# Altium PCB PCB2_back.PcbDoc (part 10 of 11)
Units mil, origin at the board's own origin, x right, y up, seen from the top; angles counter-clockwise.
Board outline 6299 x 3937 mil, 4 copper layers (TopLayer, GROUND, VCC, BottomLayer); 290 components, 470 nets, 2252 pads, 825 vias.
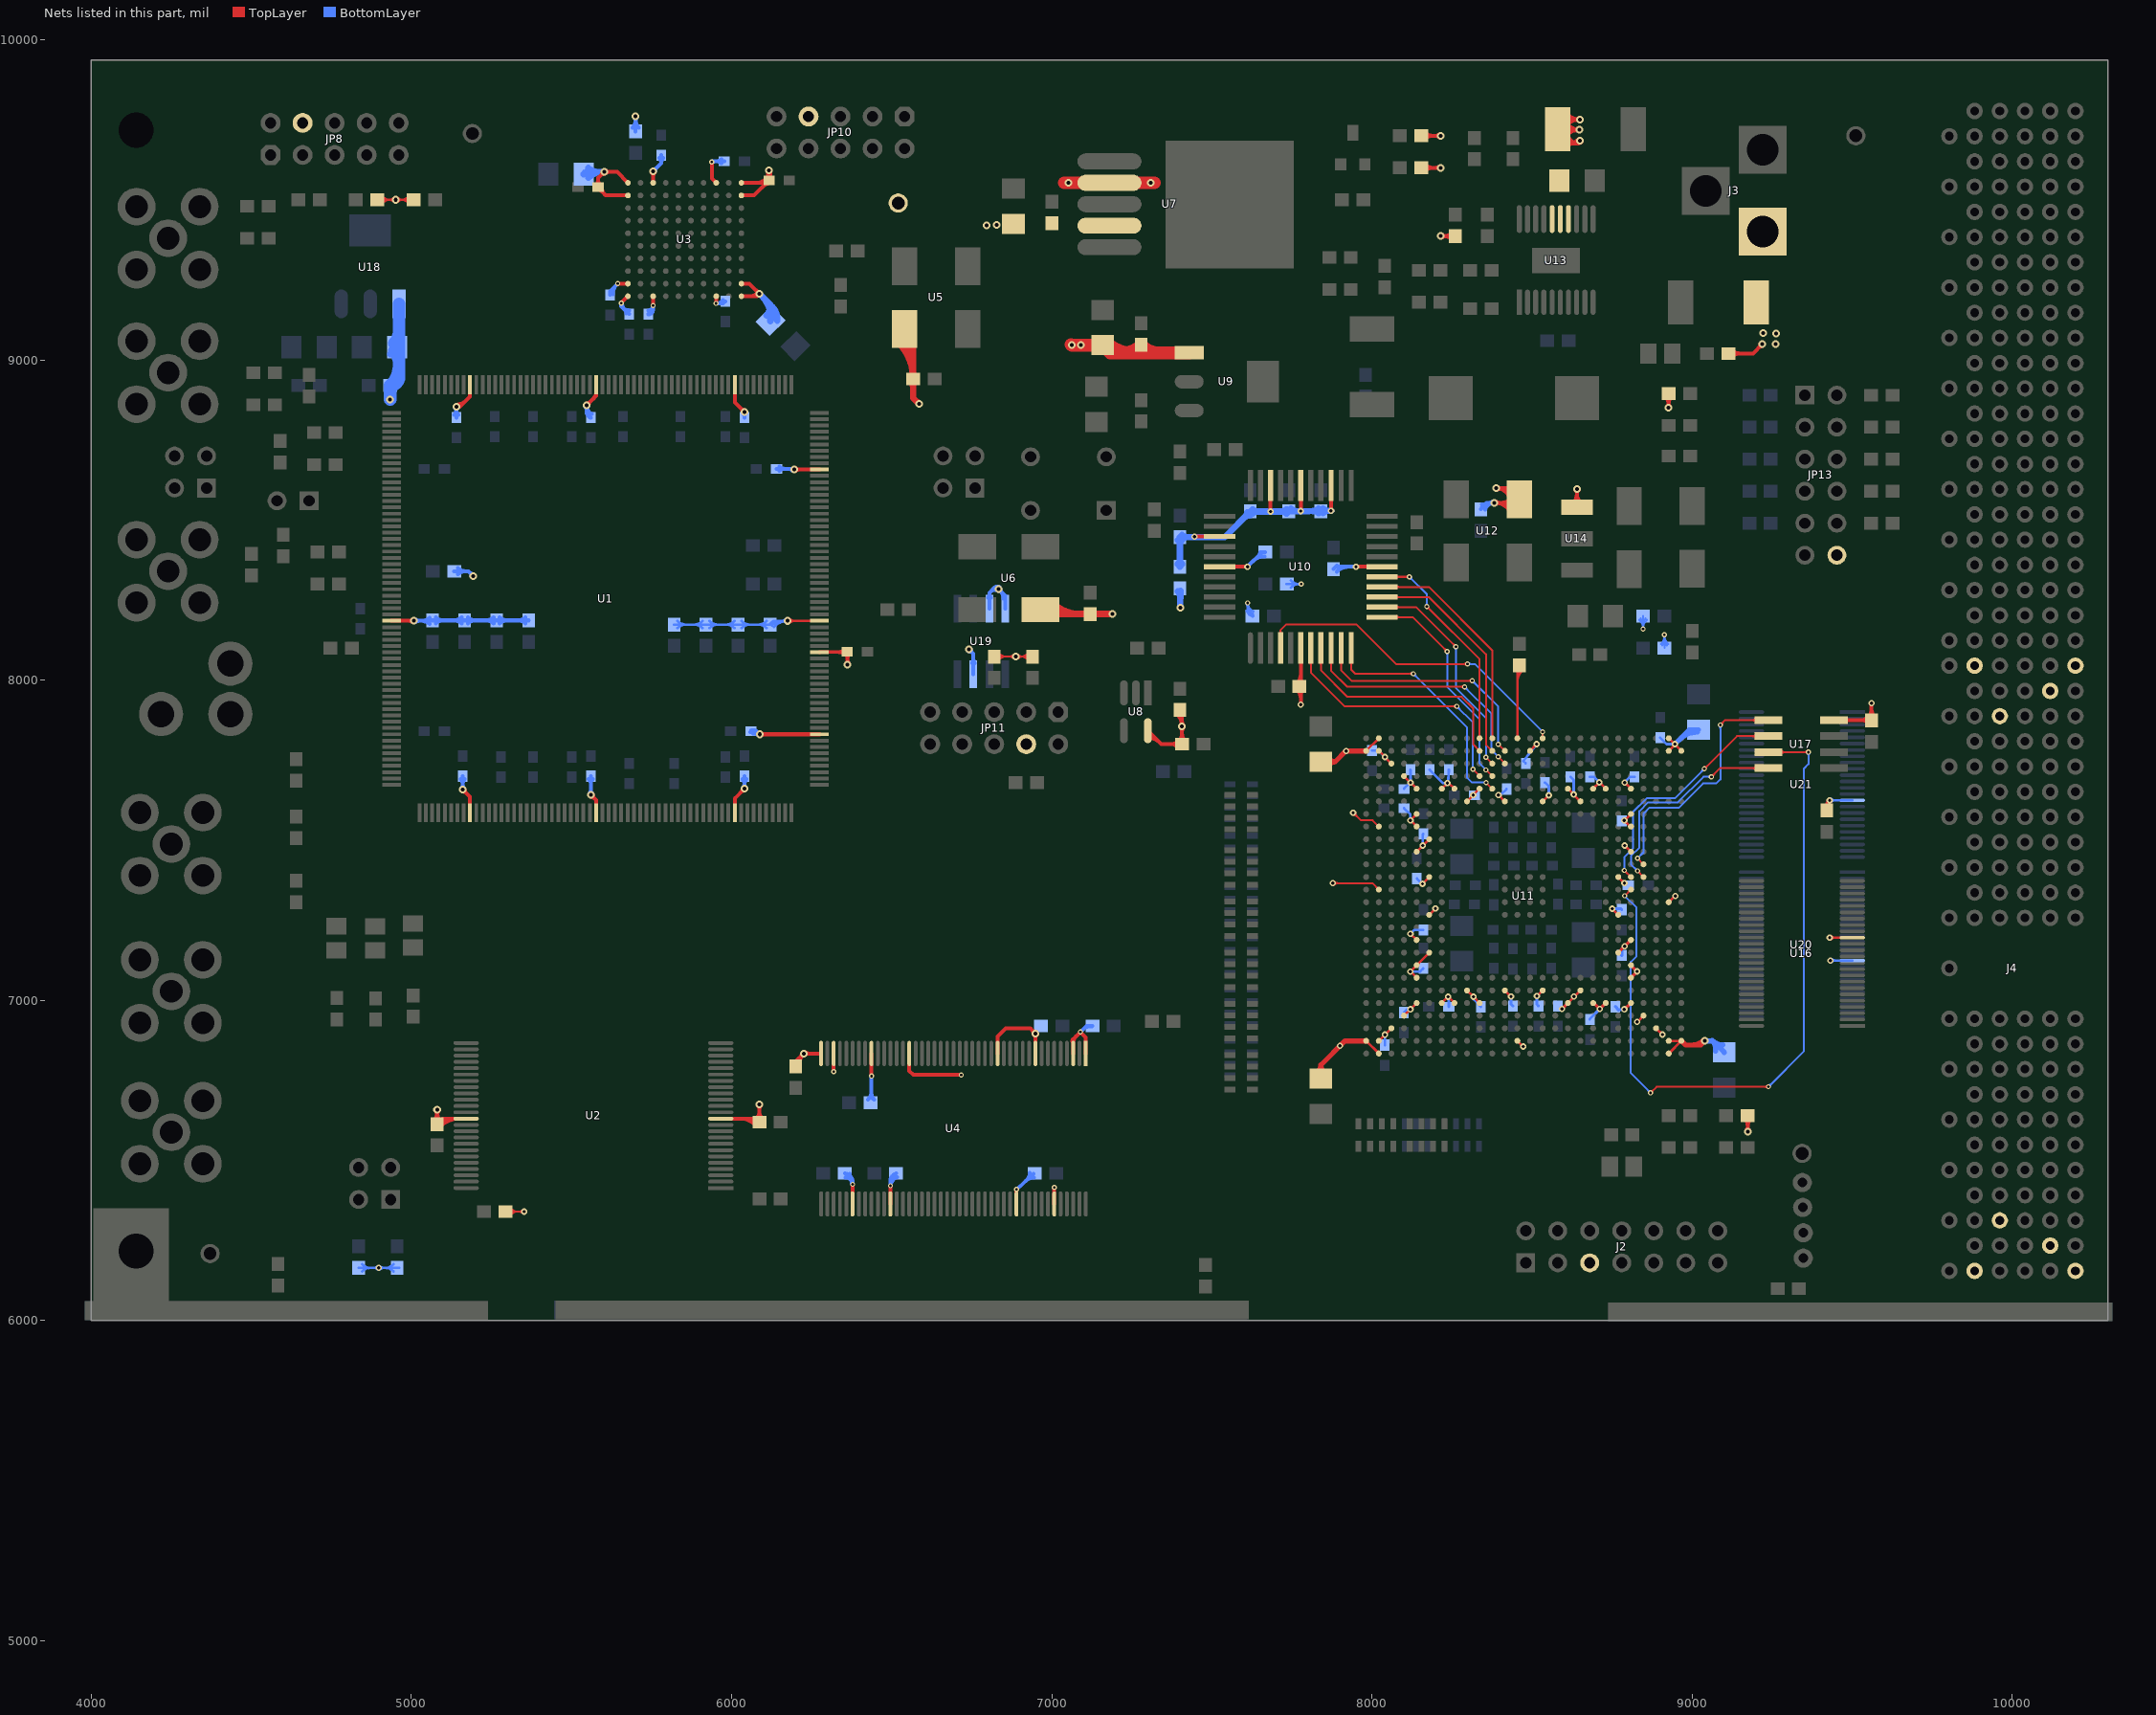
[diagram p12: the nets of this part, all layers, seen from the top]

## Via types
v1: diameter 16, hole 8, TopLayer to BottomLayer, 408 vias
v2: diameter 20, hole 10, TopLayer to BottomLayer, 221 vias
v3: diameter 24, hole 12, TopLayer to BottomLayer, 194 vias
v4: diameter 56.69, hole 56.69, TopLayer to BottomLayer, 2 vias

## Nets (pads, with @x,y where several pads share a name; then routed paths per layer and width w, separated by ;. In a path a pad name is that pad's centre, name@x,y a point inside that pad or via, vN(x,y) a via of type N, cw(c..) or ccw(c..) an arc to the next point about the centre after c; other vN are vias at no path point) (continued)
V3.3: C5.2 C6.2 C7.1 C8.2 C9.2 C10.1 C11.2 C12.1 C15.2 C16.2 C19.2 C20.1 C21.1 C22.2 C37.2 C44.1 C48.1 C55.1 C56.1 C57.1 C59.2 C62.2 C65.2 C66.2 C70.2 C71.1 C73.1 C74.2 C75.1 C77.1 C78.1 C79.2 C80.2 C81.2 C82.2 C83.2 C84.2 C86.2 C89.2 C91.1 C93.1 C94.1 C95.1 C96.1 C97.1 C98.1 C99.1 C100.1 C101.1 C102.1 C103.1 C108.1 C109.1 C110.1 C116.1 C117.2 C119.1 C120.1 C127.1 C128.1 C132.1 C133.1 C134.1 C139.1 C140.1 C141.1 C142.1 C143.1 C144.1 C145.1 C146.1 C147.1 FB4.1 FB8.2 J2.5 JP8.4 JP10.7 JP11.4 pad.9 R15.2 R18.2 R19.2 R24.2 R26.2 R30.2 R56.2 R63.1 R64.1 R65.2 R66.2 R76.1 R77.1 R80.2 R81.2 R82.2 U1.9 U1.22 U1.51 U1.70 U1.92 U1.112 U1.189 U1.209 U1.231 U2.12 U2.37 U3.A1 U3.A3 U3.A8 U3.A10 U3.B1 U3.B10 U3.J1 U3.J10 U3.K1 U3.K3 U3.K8 U3.K10 U4.1 U4.3 U4.9 U4.15 U4.29 U4.35 U4.41 U4.43 U4.49 U4.55 U4.75 U4.81 U5.4 U6.4 U7.4 U8.5 U10.6 U10.17 U10.39 U11.A2 U11.A25 U11.AA9 U11.AA12 U11.AA15 U11.AA18 U11.AB5 U11.AB7 U11.AB8 U11.AB10 U11.AB17 U11.AB19 U11.AB20 U11.AB22 U11.AC23 U11.AD24 U11.AE1 U11.AE2 U11.AE13 U11.AE25 U11.AE26 U11.AF2 U11.AF25 U11.B1 U11.B2 U11.B14 U11.B25 U11.B26 U11.C3 U11.C24 U11.D4 U11.D23 U11.E5 U11.E7 U11.E8 U11.E10 U11.E17 U11.E19 U11.E20 U11.E22 U11.F9 U11.F12 U11.F15 U11.F18 U11.G5 U11.G22 U11.H5 U11.H22 U11.J6 U11.J21 U11.K5 U11.K22 U11.M6 U11.M21 U11.N2 U11.P25 U11.R6 U11.R21 U11.U5 U11.U22 U11.V21 U11.W5 U11.W22 U11.W25 U11.Y5 U11.Y22 U12.4 U14.1 U17.8 U19.3 U19.7 U19.8 | length 16963.2
  TopLayer w6: 5124.53,6630.53 U2.37@5170.72,6630.53 ; U2.37@5135.21,6628.48 ccw(c5130.25,6623.52) 5130.25,6630.53 ccw(c5130.25,6637.55) U2.37@5135.21,6632.59 ; R19.2@5293.46,6340 v2(5352,6340) ; R19.2@5302.99,6332.44 cw(c5321.23,6314.2) 5321.23,6340 cw(c5321.23,6365.8) R19.2@5302.99,6347.56 ; R19.2@5307.23,6328.2 cw(c5335.71,6299.72) 5335.71,6340 cw(c5335.71,6380.28) R19.2@5307.23,6351.8 ; v2@5347.05,6335.05 ccw(c5335.1,6323.1) 5335.1,6340 ccw(c5335.1,6356.9) v2@5347.05,6344.95 ; R24.2@6820,8073.46 R26.2@6940,8073.46 ; R24.2@6827.56,8065.91 cw(c6845.8,8047.67) 6845.8,8073.46 cw(c6845.8,8099.26) R24.2@6827.56,8081.02 ; R24.2@6831.8,8061.67 cw(c6860.28,8033.18) 6860.28,8073.46 cw(c6860.28,8113.75) R24.2@6831.8,8085.26 ; v3@6881.64,8067.1 ccw(c6866.27,8051.74) 6866.27,8073.46 ccw(c6866.27,8095.19) v3@6881.64,8079.83 ; v3@6894.36,8067.1 cw(c6909.73,8051.74) 6909.73,8073.46 cw(c6909.73,8095.19) v3@6894.36,8079.83 ; R26.2@6928.2,8061.67 ccw(c6899.72,8033.18) 6899.72,8073.46 ccw(c6899.72,8113.75) R26.2@6928.2,8085.26 ; R26.2@6932.44,8065.91 ccw(c6914.2,8047.67) 6914.2,8073.46 ccw(c6914.2,8099.26) R26.2@6932.44,8081.02 ; v2(7877,7366) 8000.93,7366 U11.P25@8021.12,7345.81 ; v2@7881.95,7361.05 cw(c7893.9,7349.1) 7893.9,7366 cw(c7893.9,7382.9) v2@7881.95,7370.95 ; v2@7941,7579 cw(c7941,7562.1) 7952.95,7574.05 cw(c7964.9,7586) v2@7948,7586 ; v2(7941,7586) 7965,7562 8001.78,7562 U11.W25@8021.12,7542.66
  TopLayer w8: R15.2@4893.46,9500 R18.2@5006.54,9500 ; R15.2@4906.52,9488.91 cw(c4933.3,9462.13) 4933.3,9500 cw(c4933.3,9537.87) R15.2@4906.52,9511.09 ; v3@4945.34,9494.34 ccw(c4931.69,9480.69) 4931.69,9500 ccw(c4931.69,9519.31) v3@4945.34,9505.66 ; v3@4956.66,9494.34 cw(c4970.31,9480.69) 4970.31,9500 cw(c4970.31,9519.31) v3@4956.66,9505.66 ; R18.2@4993.48,9488.91 ccw(c4966.7,9462.13) 4966.7,9500 ccw(c4966.7,9537.87) R18.2@4993.48,9511.09 ; U11.B26@7981.75,6873.37 U11.A25@8021.12,6834 ; U11.AE26@7981.75,7778.88 U11.AF25@8021.12,7818.25 ; U11.B25@8021.12,6873.37 U11.C24@8060.49,6912.74 ; U11.AE25@8021.12,7778.88 U11.AD24@8060.49,7739.51 ; U11.D23@8099.86,6952.11 8119.87,6972.13 U11.E22@8139.23,6991.48 ; U11.AC23@8099.86,7700.14 U11.AB22@8139.23,7660.77 ; v2(8120,7207.56) U11.K22@8139.23,7188.33 ; U11.G22@8139.23,7070.22 8139.23,7070.41 v2(8119.64,7090) U11.J21@8178.6,7148.96 ; U11.U22@8139.23,7463.92 U11.V21@8178.6,7503.29 ; U11.W22@8139.23,7542.66 v2(8120,7561.89) 8120,7562.8 U11.Y22@8139.23,7582.03 ; v2(8157.42,7364) U11.R21@8178.6,7385.18 ; U11.M21@8178.6,7267.07 v2(8198,7286.47) ; U11.E20@8217.97,6991.48 8237.49,7011 v2(8237.82,7011) U11.E19@8257.34,6991.48 ; U11.AB20@8217.97,7660.77 v2(8235.2,7678) 8240.11,7678 U11.AB19@8257.34,7660.77 ; U11.F18@8296.71,7030.85 8297.15,7030.85 v2(8317,7011) U11.E17@8336.08,6991.48 ; U11.AA18@8296.71,7621.4 U11.AB17@8336.08,7660.77 ; v2(8395,7641.22) U11.AA15@8414.82,7621.4 ; U11.F15@8414.82,7030.85 v2(8434,7011.67) ; U11.B14@8454.19,6873.37 v2(8472,6855.56) ; U11.AE13@8493.56,7778.88 v2(8514,7800) ; v2(8515,7012.92) U11.F12@8532.93,7030.85 ; U11.AA12@8532.93,7621.4 v2(8552,7640.47) ; U11.E10@8611.67,6991.48 U11.F9@8651.04,7030.85 ; U11.AB10@8611.67,7660.77 U11.AA9@8651.04,7621.4 ; U11.AB8@8690.41,7660.77 8710,7680.36 v2(8710,7680.55) U11.AB7@8729.78,7660.77 ; v2(8750,7286.22) U11.M6@8769.15,7267.07 ; U11.R6@8769.15,7385.18 v2(8788.33,7366) ; v2(8789,7483.44) U11.U5@8808.52,7463.92 ; v2(8789,7680.29) U11.AB5@8808.52,7660.77 ; U11.W5@8808.52,7542.66 8806.85,7542.66 v2(8788,7561.51) U11.Y5@8808.52,7582.03 ; v2(8828,6932.22) U11.D4@8847.89,6952.11 ; U11.C3@8887.26,6912.74 v2(8907,6893) ; U11.A2@8926.63,6834 U11.B1@8966,6873.37 U11.B2@8926.63,6873.37 ; U11.N2@8926.63,7306.44 v2(8947,7326) ; U11.AE2@8926.63,7778.88 8946,7798.25 v2(8946,7800) ; U11.AF2@8926.63,7818.25 U11.AE1@8966,7778.88
  TopLayer w10: v2(8593.19,6973) U11.E10@8611.67,6991.48 ; U11.E8@8690.41,6991.48 8692.82,6991.48 v2(8711.3,6973) U11.E7@8729.78,6991.48 ; U11.J6@8769.15,7148.96 v2(8788.91,7168.72) U11.K5@8808.52,7188.33 ; v2(8788,6972) U11.E5@8808.52,6991.48 ; U11.G5@8808.52,7070.22 8828,7089.7 v2(8828,7090.11) U11.H5@8808.52,7109.59
  TopLayer w12: C5.2@5070.32,6625.11 ccw(c5046.96,6648.47) 5080,6648.47 ccw(c5113.04,6648.47) C5.2@5089.68,6625.11 ; v3@5075.76,6653.76 cw(c5065.51,6643.51) 5080,6643.51 cw(c5094.49,6643.51) v3@5084.24,6653.76 ; v3(5080,6658) C5.2@5080,6613.46 5097.07,6630.53 U2.37@5170.72,6630.53 ; C5.2@5081.19,6614.24 cw(c5120.53,6574.91) 5120.53,6630.53 ; C5.2@5089.68,6605.76 cw(c5149.5,6545.94) U2.37@5149.5,6630.53 ; v3(5140,8854) 5151,8854 5182.77,8885.77 U1.112@5182.77,8922.31 ; v3@5140,8860 ccw(c5140,8901.04) 5169.02,8872.02 ; v3@5160,7652 cw(c5160,7637.51) 5170.24,7647.76 cw(c5180.49,7658) v3@5166,7658 ; v3(5160,7658) 5182.77,7635.23 U1.189@5182.77,7585.69 ; v3(5547,8858) 5576.47,8887.47 U1.92@5576.47,8922.31 ; v3@5547,8864 ccw(c5547,8878.49) 5557.24,8868.24 ccw(c5567.49,8858) v3@5553,8858 ; v3@5560,7636 cw(c5560,7621.51) 5570.24,7631.76 cw(c5580.49,7642) v3@5566,7642 ; v3(5560,7642) 5576.47,7625.53 U1.209@5576.47,7585.69 ; 5568.71,8879.71 ccw(c5549.73,8898.68) U1.92@5576.57,8898.68 ; C6.2@5576.63,9546.36 ccw(c5561.26,9561.73) 5582.99,9561.73 ccw(c5604.72,9561.73) C6.2@5589.36,9546.36 ; C6.2@5594.49,9539.66 ccw(c5625.73,9538.49) 5603.62,9516.38 ; v3@5596,9587 cw(c5581.51,9587) 5591.76,9576.76 cw(c5602,9566.51) v3@5602,9581 ; v3@5606.24,9582.76 cw(c5616.49,9572.51) 5616.49,9587 cw(c5616.49,9601.49) v3@5606.24,9591.24 ; v1(5644.04,9238.04) U3.J1@5676,9238.04 ; v1(5655,9177.67) U3.K1@5676,9198.67 ; U3.B1@5676,9513.63 5606.37,9513.63 5582.99,9537.01 5582.99,9567.99 v3(5602,9587) 5642,9587 U3.A1@5676,9553 ; v3@5750.5,9584.5 cw(c5740.25,9574.25) 5754.74,9574.25 cw(c5769.23,9574.25) v3@5758.98,9584.5 ; v1(5754.74,9169.74) U3.K3@5754.74,9198.67 ; U3.A3@5754.74,9553 v3(5754.74,9588.74) ; v1(5938,9618) 5938,9566.59 U3.A8@5951.59,9553 ; v1(5951.59,9176.41) U3.K8@5951.59,9198.67 ; U2.12@5966,6630.53 6076,6630.53 C7.1@6086.54,6620 v3(6086.54,6674.54) ; U1.231@6009.54,7585.69 6009.54,7630.54 v3(6040,7661) ; U1.70@6009.54,8922.31 6009.54,8867.46 v3(6040,8837) ; 6026.09,6630.53 cw(c6026.09,6561.53) C7.1@6074.89,6610.32 ; U3.K10@6030.33,9198.67 6079.67,9198.67 v3(6087,9206) 6054.96,9238.04 U3.J10@6030.33,9238.04 ; U3.B10@6030.33,9513.63 6070.64,9513.63 C9.2@6117.01,9560 ; U3.A10@6030.33,9553 C9.2@6110.01,9553 ; v3@6034,7661 cw(c6019.51,7661) 6029.76,7650.76 cw(c6040,7640.51) v3@6040,7655 ; v3@6034,8837 ccw(c6019.51,8837) 6029.76,8847.24 ccw(c6040,8857.49) v3@6040,8843 ; 6054.82,9198.67 ccw(c6054.82,9238.18) v3@6082.76,9210.24 ; 6055.07,6630.53 cw(c6055.07,6590.5) C7.1@6083.38,6618.81 ; 6075.88,9553 ccw(c6075.88,9598.63) C9.2@6108.14,9566.36 ; C7.1@6076.86,6629.68 ccw(c6053.5,6653.04) 6086.54,6653.04 ccw(c6119.57,6653.04) C7.1@6096.21,6629.68 ; v3@6081,9206 ccw(c6066.51,9206) 6076.76,9216.24 ccw(c6087,9226.49) v3@6087,9212 ; v3@6082.29,6670.29 cw(c6072.05,6660.05) 6086.54,6660.05 cw(c6101.02,6660.05) v3@6090.78,6670.29 ; v3(6087.23,7830.77) U1.9@6274.31,7830.77 ; v3@6091.47,7826.53 cw(c6101.71,7816.29) 6101.71,7830.77 cw(c6101.71,7845.26) v3@6091.47,7835.01 ; 6097.38,9540.37 ccw(c6077.74,9560) C9.2@6105.51,9560 ; C9.2@6103.41,9546.4 cw(c6114.51,9535.31) C9.2@6114.51,9551 ; v3(6195.46,8657.54) U1.51@6274.31,8657.54 ; v3@6199.7,8653.3 cw(c6209.94,8643.06) 6209.94,8657.54 cw(c6209.94,8672.03) v3@6199.7,8661.79 ; C8.2@6200,6793.46 6200,6809 v3(6225,6834) ; C8.2@6201.66,6795.72 cw(c6226.28,6799.95) 6208.61,6817.61 ; C8.2@6213.49,6797.75 cw(c6254.24,6804.76) v3(6225,6834) ; v3@6219,6834 cw(c6204.51,6834) 6214.76,6823.76 cw(c6225,6813.51) v3@6225,6828 ; v3@6229.24,6829.76 cw(c6239.49,6819.51) 6239.49,6834 cw(c6239.49,6848.49) v3@6229.24,6838.24 ; U1.22@6274.31,8086.68 C10.1@6361,8088 6362,8089 v3(6362,8048) ; U4.43@6279.23,6834 v3(6225,6834) ; v1(6318.6,6777.6) U4.41@6318.6,6834 ; 6336.68,8087.63 ccw(c6336.35,8109.48) C10.1@6352.04,8094.27 ; 6336.87,8087.63 cw(c6337.2,8066.04) C10.1@6352.23,8081.54 ; C10.1@6354.64,8081.64 cw(c6336.86,8063.86) 6362,8063.86 ; v3@6357.76,8052.24 ccw(c6347.51,8062.49) 6362,8062.49 ccw(c6376.49,8062.49) v3@6366.24,8052.24 ; 6362,8068.69 cw(c6380.31,8068.69) C10.1@6367.36,8081.64 ; U4.49@6377.65,6364 v1(6377.65,6425.35) ; v1(6436.71,6763.29) U4.35@6436.71,6834 ; U4.55@6495.77,6364 v1(6495.77,6420.77) ; U4.29@6554.82,6834 6554.82,6779.18 6567,6767 v1(6717,6767) ; U4.15@6830.41,6834 6830.41,6886.41 6856,6912 6933,6912 v3(6948.52,6896.48) U4.9@6948.52,6834 ; U4.75@6889.47,6364 v1(6889.47,6409.47) ; v3@6942.52,6896.48 ccw(c6928.03,6896.48) 6938.28,6906.72 ccw(c6948.52,6916.97) v3@6948.52,6902.48 ; v3@6944.28,6892.24 cw(c6934.03,6881.99) 6948.52,6881.99 cw(c6963.01,6881.99) v3@6952.76,6892.24 ; U4.81@7007.57,6364 v1(7007.57,6415.57) ; U4.3@7066.56,6867.4 cw(c7072.28,6872.98) 7066.63,6878.63 ; U4.3@7066.54,6867.46 cw(c7093.26,6867.46) 7074.36,6886.36 ; U4.3@7066.63,6834 7066.63,6878.63 ; U4.1@7106,6834 7106,6884 v1(7089,6901) 7066.63,6878.63 ; U8.5@7299.6,7832.52 cw(c7300.09,7810.12) 7315.93,7825.96 ; U8.5@7299.86,7820.52 cw(c7300.94,7771.23) 7335.8,7806.09 ; U8.5@7300,7841.89 7341.89,7800 C19.2@7406.54,7800 7406.54,7900 R30.2@7400,7906.54 ; R30.2@7390.32,7894.89 cw(c7351.18,7855.75) v3@7406.54,7855.75 ; C19.2@7394.89,7790.32 ccw(c7371.53,7766.96) 7371.53,7800 ccw(c7371.53,7833.04) C19.2@7394.89,7809.68 ; C19.2@7396.86,7809.68 ccw(c7373.5,7833.04) 7406.54,7833.04 ccw(c7439.57,7833.04) C19.2@7416.21,7809.68 ; R30.2@7398.81,7903.38 cw(c7380.15,7884.72) 7406.54,7884.72 ; v3@7402.29,7850.76 cw(c7392.05,7840.51) 7406.54,7840.51 cw(c7421.02,7840.51) v3@7410.78,7850.76 ; v3@7402.29,7859.24 ccw(c7392.05,7869.49) 7406.54,7869.49 ccw(c7421.02,7869.49) v3@7410.78,7859.24 ; U10.39@7523.54,8353.94 v2(7610.94,8353.94) ; C22.2@7765.76,7970.32 cw(c7737.45,7942.02) 7777.48,7942.02 ; C22.2@7765.76,7989.68 ccw(c7737.45,8017.98) 7777.48,8017.98 ; v2(7777.48,7923.48) U10.6@7777.48,8100 ; 7777.48,7951.9 cw(c7803.53,7951.9) C22.2@7785.11,7970.32 ; 7777.48,8008.1 ccw(c7803.53,8008.1) C22.2@7785.11,7989.68 ; v2(7949.94,8353.94) U10.17@8031.42,8353.94 ; v3@8386.24,8549.76 cw(c8396.49,8539.51) 8396.49,8554 cw(c8396.49,8568.49) v3@8386.24,8558.24 ; v3@8392.24,8594.76 cw(c8402.49,8584.51) 8402.49,8599 cw(c8402.49,8613.49) v3@8392.24,8603.24 ; 8402.82,8554 ccw(c8402.82,8601.5) U12.4@8436.4,8567.91 ; 8403.74,8554 cw(c8403.74,8508.88) U12.4@8441.92,8532.93 ; 8405.75,8599 cw(c8405.75,8561.91) U12.4@8440.17,8575.73 ; 8416.41,8599 ccw(c8416.41,8627.27) U12.4@8436.4,8607.28 ; U12.4@8423.5,8599 cw(c8423.5,8569.04) U12.4@8451.3,8580.2 ; U12.4@8429.03,8571.26 ccw(c8388,8554.79) v3(8388,8599) U12.4@8458,8599 ; U12.4@8431.76,8526.53 ccw(c8382,8495.19) v3(8382,8554) U12.4@8463,8554 ; U14.1@8627.54,8552.46 ccw(c8597.46,8582.54) 8640,8582.54 ccw(c8682.54,8582.54) U14.1@8652.46,8552.46 ; v3@8635.76,8592.76 cw(c8625.51,8582.51) 8640,8582.51 cw(c8654.49,8582.51) v3@8644.24,8592.76 ; U14.1@8640,8540 v3(8640,8597) ; FB4.1@8916.74,8885.44 cw(c8893.11,8862.36) 8926.14,8861.96 cw(c8959.18,8861.57) FB4.1@8936.1,8885.21 ; v3@8921.81,8854.29 ccw(c8911.69,8864.66) 8926.17,8864.48 ccw(c8940.66,8864.31) v3@8930.29,8854.19 ; v3(8926,8850) FB4.1@8926.54,8895 ; R56.2@9163.79,6630.32 cw(c9140.43,6606.96) 9173.46,6606.96 cw(c9206.5,6606.96) R56.2@9183.14,6630.32 ; v3@9169.22,6594.24 ccw(c9158.98,6604.49) 9173.46,6604.49 ccw(c9187.95,6604.49) v3@9177.71,6594.24 ; v3(9173.47,6590) R56.2@9173.46,6640 ; U17.8@9442.36,7875 9558.46,7875 C37.2@9560,7873.46 v2(9560,7928) ; U17.8@9477.97,7870.89 cw(c9487.89,7860.97) 9487.89,7875 cw(c9487.89,7889.03) U17.8@9477.97,7879.11 ; 9525.92,7875 ccw(c9525.92,7909.52) 9550.32,7885.11 ccw(c9526.96,7908.47) 9560,7908.47 ccw(c9593.04,7908.47) C37.2@9569.68,7885.11 ; 9528.01,7875 cw(c9528.01,7843.44) C37.2@9550.32,7865.76
  TopLayer w16: C20.1@7827.36,6774.92 ccw(c7812.62,6798) 7840,6798 ; C20.1@7840,6755.12 7840,6798 ; C21.1@7840,7744.88 7884.88,7744.88 ; C20.1@7852.64,6774.92 cw(c7867.38,6798) 7840,6798 ; C21.1@7864.22,7733.03 cw(c7884.88,7720.96) 7884.88,7744.88 ; C21.1@7864.22,7756.74 ccw(c7884.88,7768.81) 7884.88,7744.88 ; U11.B26@7981.75,6873.37 7915.37,6873.37 7840,6798 ; U11.AE26@7981.75,7778.88 v2(7918.88,7778.88) 7884.88,7744.88 ; U11.B1@8966,6873.37 8979.37,6860 9026.26,6860 v3(9039.63,6873.37) ; 8997.69,6860 ccw(c8997.69,6915.31) v3@9036.8,6876.2
  TopLayer w20: C9.2@6117.01,9560 v3(6117.01,9591.99) ; U5.4@6519.23,9055.55 cw(c6405.03,8941.35) C11.2@6566.54,8941.35 ; U5.4@6533.37,9069.69 cw(c6453.32,8989.63) 6566.54,8989.63 ; U5.4@6540,9096 6566.54,9069.46 6566.54,8881.46 v3(6585,8863) ; U5.4@6547.52,9083.83 cw(c6501.6,9037.92) U5.4@6566.54,9037.92 ; C11.2@6559.69,8933.15 cw(c6543.15,8916.62) 6566.54,8916.62 cw(c6589.92,8916.62) C11.2@6573.38,8933.15 ; C11.2@6559.69,8946.85 ccw(c6543.15,8963.38) 6566.54,8963.38 ccw(c6589.92,8963.38) C11.2@6573.38,8946.85 ; U6.4@6964,8220 6977.46,8206.54 v3(7189.54,8206.54) ; U6.4@6990.31,8226.63 ccw(c7038.81,8275.13) 7038.81,8206.54 ; U6.4@7004.45,8199.23 cw(c7022.08,8181.6) U6.4@7022.08,8206.54 ; U6.4@7004.45,8240.77 ccw(c7087.1,8323.41) 7087.1,8206.54 ; C16.2@7113.15,8199.69 ccw(c7096.62,8183.15) 7096.62,8206.54 ccw(c7096.62,8229.92) C16.2@7113.15,8213.38 ; C16.2@7126.85,8199.69 cw(c7143.38,8183.15) 7143.38,8206.54 cw(c7143.38,8229.92) C16.2@7126.85,8213.38
  TopLayer w40: C12.1@6880,9417 C12.1@6880.05,9417
  BottomLayer w6: R80.2@8834.74,8188.2 cw(c8806.25,8159.72) 8846.54,8159.72 cw(c8886.82,8159.72) R80.2@8858.33,8188.2 ; R80.2@8838.98,8192.44 cw(c8820.74,8174.2) 8846.54,8174.2 cw(c8872.33,8174.2) R80.2@8854.09,8192.44 ; v1@8843,8163.07 ccw(c8834.46,8171.61) 8846.54,8171.61 ccw(c8858.61,8171.61) v1@8850.07,8163.07 ; v1(8846.54,8159.54) R80.2@8846.54,8200 ; R82.2@8901.67,8111.8 ccw(c8873.18,8140.28) 8913.46,8140.28 ccw(c8953.75,8140.28) R82.2@8925.26,8111.8 ; R82.2@8905.91,8107.56 ccw(c8887.67,8125.8) 8913.46,8125.8 ccw(c8939.26,8125.8) R82.2@8921.02,8107.56 ; v1@8909.93,8137.93 cw(c8901.39,8129.39) 8913.46,8129.39 cw(c8925.54,8129.39) v1@8917,8137.93 ; R82.2@8913.46,8100 v1(8913.46,8141.46)
  BottomLayer w8: R63.1@4835,6164.54 R64.1@4961.54,6164.54 ; R63.1@4846.09,6153.44 cw(c4872.87,6126.67) 4872.87,6164.54 cw(c4872.87,6202.4) R63.1@4846.09,6175.63 ; v2@4893.76,6160.29 ccw(c4883.51,6150.05) 4883.51,6164.54 ccw(c4883.51,6179.02) v2@4893.76,6168.78 ; v2@4902.24,6160.29 cw(c4912.49,6150.05) 4912.49,6164.54 cw(c4912.49,6179.02) v2@4902.24,6168.78 ; R64.1@4943.91,6153.44 ccw(c4917.13,6126.67) 4917.13,6164.54 ccw(c4917.13,6202.4) R64.1@4943.91,6175.63 ; v1@7608.17,8238.17 cw(c7601.34,8231.34) 7611,8231.34 cw(c7620.66,8231.34) v1@7613.83,8238.17 ; R77.1@7611,8215.54 v1(7611,8241) ccw(c7638.67,8241) R77.1@7629.67,8214.83 ; R77.1@7611,8218.57 ccw(c7630.96,8218.57) R77.1@7624.46,8199.7 ; 7611,8229.79 ccw(c7634.81,8229.79) R77.1@7627.07,8207.27 ; R76.1@7733.46,8300 v1(7779,8300) ; R76.1@7746.52,8288.91 cw(c7773.3,8262.13) 7773.3,8300 cw(c7773.3,8337.87) R76.1@7746.52,8311.09 ; v1@7776.17,8297.17 ccw(c7769.34,8290.34) 7769.34,8300 ccw(c7769.34,8309.66) v1@7776.17,8302.83 ; C91.1@8000,7780 8020,7780 v2(8040,7760) ; C93.1@8040,6860 8040.55,6860.55 v2(8040.55,6892.81) ; C96.1@8099.86,7660.77 8118.71,7679.63 v2(8120.37,7679.63) 8120.37,7719.63 C97.1@8120,7720 ; C94.1@8100,6962 8110,6972 v2(8120,6972) ; C95.1@8100,7600 8120,7580 v2(8120,7561.89) ; v2(8119.64,7090) 8150,7090 C99.1@8160,7100 ; v2(8120,7207.56) 8132.44,7220 C100.1@8160,7220 ; C101.1@8140,7380 8156,7364 v2(8157.42,7364) ; v2(8158.69,7483.39) 8158.69,7518.69 C102.1@8160,7520 ; C103.1@8180,7720 8222,7678 8238,7678 C109.1@8240,7720 ; v2(8237.82,7011) 8240,7008.82 C98.1@8240,6980 ; v2(8317,7011) 8317,7003 C110.1@8340,6980 ; v2(8395,7641.22) 8401.22,7641.22 C116.1@8420,7660 ; v2(8434,7011.67) 8434,6988 C119.1@8440,6982 ; C127.1@8480,7740 8473,7747 8493,7773 v2(8514,7800) ; v2(8515,7012.92) 8515,6987 C120.1@8520,6982 ; C132.1@8540,7680 8552,7668 v2(8552,7640.47) ; C133.1@8620,7698 8630,7688 v2(8630,7643) ; C134.1@8680,6940 8680,6941.7 v2(8711.3,6973) ; C139.1@8680,7698 8692.55,7698 v2(8710,7680.55) ; v2(8750,7286.22) 8776.77,7286.22 R81.2@8780,7282.99 ; v2(8789,7680.29) 8806.71,7698 C144.1@8820,7698 ; C145.1@8900,7820 8920,7800 v2(8946,7800)
  BottomLayer w10: C140.1@8760,6980 8770,6970 v2(8788,6972) ; C141.1@8780,7140 8780,7159.81 v2(8788.91,7168.72)
  BottomLayer w12: R65.2@5133.46,8340 5178,8340 v3(5193,8325) ; C48.1@5133.64,8828.86 ccw(c5118.27,8844.23) 5140,8844.23 ccw(c5161.73,8844.23) C48.1@5146.36,8828.86 ; v3@5135.76,8849.76 cw(c5125.51,8839.51) 5140,8839.51 cw(c5154.49,8839.51) v3@5144.24,8849.76 ; C48.1@5140,8820 v3(5140,8854) ; R65.2@5145.11,8330.32 cw(c5168.47,8306.96) 5168.47,8340 cw(c5168.47,8373.04) R65.2@5145.11,8349.68 ; C44.1@5153.64,7691.14 cw(c5138.27,7675.77) 5160,7675.77 cw(c5181.73,7675.77) C44.1@5166.36,7691.14 ; v3@5155.76,7662.24 ccw(c5145.51,7672.49) 5160,7672.49 ccw(c5174.49,7672.49) v3@5164.24,7662.24 ; v3(5160,7658) C44.1@5160,7700 ; v3@5187,8325 ccw(c5172.51,8325) 5182.76,8335.24 ccw(c5193,8345.49) v3@5193,8331 ; v3@5542.76,8853.76 cw(c5532.51,8843.51) 5547,8843.51 cw(c5561.49,8843.51) v3@5551.24,8853.76 ; 5547,8838.64 ccw(c5568.02,8838.64) C57.1@5558.66,8819.81 ; C56.1@5553.64,7691.14 cw(c5538.27,7675.77) 5560,7675.77 cw(c5581.73,7675.77) C56.1@5566.36,7691.14 ; v3@5555.76,7646.24 ccw(c5545.51,7656.49) 5560,7656.49 ccw(c5574.49,7656.49) v3@5564.24,7646.24 ; v3(5560,7642) C56.1@5560,7700 ; C57.1@5560,8820 5547,8833 v3(5547,8858) ccw(c5577.64,8858) C57.1@5564.01,8830.56 ; C59.2@5620,9202.99 5620,9214 v1(5644.04,9238.04) ; C59.2@5629,9205.49 cw(c5671.27,9205.49) v1@5641.38,9235.38 ; v1(5655,9177.67) 5655,9167.99 C62.2@5680,9142.99 ; v1@5657,9177.67 ccw(c5685.19,9177.67) C62.2@5665.26,9157.74 ; 5660.37,9162.62 ccw(c5680,9182.26) C62.2@5680,9154.49 ; C62.2@5666.4,9156.59 cw(c5655.31,9145.49) C62.2@5671,9145.49 ; R66.2@5690.32,9725.11 ccw(c5666.96,9748.47) 5700,9748.47 ccw(c5733.04,9748.47) R66.2@5709.68,9725.11 ; v3@5695.76,9756.76 cw(c5685.51,9746.51) 5700,9746.51 cw(c5714.49,9746.51) v3@5704.24,9756.76 ; R66.2@5700,9713.46 v3(5700,9761) ; C65.2@5739.81,9154.49 ccw(c5739.49,9169.74) v1(5754.74,9169.74) 5754.74,9157.73 C65.2@5740,9142.99 ; C65.2@5740.06,9142.49 ccw(c5739.75,9157.48) C65.2@5754.74,9157.48 ; C65.2@5746,9149 ccw(c5729.07,9165.93) v1@5752.76,9169.45 ; v3(5754.74,9588.74) 5780,9614 C66.2@5780,9639.01 ; v3@5754.74,9594.74 ccw(c5754.74,9609.23) 5764.98,9598.98 ccw(c5775.23,9588.74) v3@5760.74,9588.74 ; C66.2@5773.64,9630.14 cw(c5758.27,9614.78) 5780,9614.78 cw(c5801.73,9614.78) C66.2@5786.36,9630.14 ; v1(5938,9618) 5940,9620 C74.2@5977.01,9620 ; v1@5939.41,9616.59 cw(c5947.66,9608.34) 5947.66,9620 ; C74.2@5968.14,9613.64 ccw(c5952.78,9598.27) 5952.78,9620 ccw(c5952.78,9641.73) C74.2@5968.14,9626.36 ; C70.2@5973.16,9186.34 cw(c5951.59,9204.79) v1(5951.59,9176.41) 5973.42,9176.41 C70.2@5980,9182.99 ; C75.1@6033.64,7691.14 cw(c6018.27,7675.77) 6040,7675.77 cw(c6061.73,7675.77) C75.1@6046.36,7691.14 ; v3@6035.76,7665.24 ccw(c6025.51,7675.49) 6040,7675.49 ccw(c6054.49,7675.49) v3@6044.24,7665.24 ; C77.1@6035.76,8832.76 cw(c6025.51,8822.51) 6040,8822.51 cw(c6054.49,8822.51) C77.1@6044.24,8832.76 ; v3(6040,7661) C75.1@6040,7700 ; C77.1@6040,8820 v3(6040,8837) ; C71.1@6061.75,7842.91 cw(c6066.54,7824.31) v3@6080.11,7837.89 ; C71.1@6067.37,7832.43 cw(c6076.21,7818.71) v3@6087.75,7830.25 ; C71.1@6068.86,7833.64 cw(c6079.4,7823.1) v3@6079.4,7838 ; C71.1@6070.61,7843.9 ccw(c6080,7848.42) v3@6080,7838 ; v3@6082.72,7826.81 ccw(c6058,7805.1) 6058,7838 v3@6080,7838 ; v3(6087.23,7830.77) v3@6080,7838 ; C73.1@6140,8660 6193,8660 v3(6195.46,8657.54) ; C73.1@6148.86,8653.64 cw(c6164.23,8638.27) 6164.23,8660 cw(c6164.23,8681.73) C73.1@6148.86,8666.36 ; 6175.04,8660 cw(c6175.04,8637.13) v3@6191.21,8653.3 ; C79.2@6353.46,6460 6377.65,6435.81 v1(6377.65,6425.35) ; C79.2@6355.2,6458.33 cw(c6351.67,6432.59) v1@6377.65,6432.59 ; C79.2@6355.43,6446.32 cw(c6355.43,6418.03) 6375.43,6438.03 ; C79.2@6366.84,6446.62 cw(c6345.56,6425.35) v1@6375.65,6425.35 ; C79.2@6369.04,6458.51 ccw(c6395.48,6455.61) 6376.67,6436.79 ; C80.2@6425.76,6689.68 ccw(c6399.31,6716.12) 6436.71,6716.12 ; 6436.71,6709.96 ccw(c6465.39,6709.96) C80.2@6445.11,6689.68 ; v1(6436.71,6763.29) 6436.71,6696.75 C80.2@6440,6693.46 ; v1@6495.76,6417.73 cw(c6527.16,6417.73) C81.2@6516.25,6447.17 ; v1(6495.77,6420.77) 6495.77,6442.3 C81.2@6513.46,6460 ; 6495.77,6434.97 cw(c6520.77,6434.97) C81.2@6512.08,6458.42 ; v3@6741,8090 cw(c6741,8075.51) 6751.24,8085.76 cw(c6761.49,8096) v3@6747,8096 ; v3(6741,8096) 6755,8082 U19.3@6755,8017.64 ; U19.3@6750.89,8053.24 ccw(c6740.97,8063.16) 6755,8063.16 ccw(c6769.03,8063.16) U19.3@6759.11,8053.24 ; U19.7@6800.89,8257.97 ccw(c6790.97,8267.89) 6805,8267.89 ccw(c6819.03,8267.89) U19.7@6809.11,8257.97 ; U19.7@6805,8222.36 6805,8273 6817,8285 v3(6833,8285) 6855,8263 U19.8@6855,8222.36 ; 6809,8277 cw(c6821.33,8264.67) v3@6830.01,8279.8 ; 6816.41,8284.41 cw(c6832.35,8268.46) v3@6833.23,8291 ; 6820.09,8288.09 cw(c6829.42,8278.76) v3@6835.99,8290.2 ; v3@6828.76,8280.76 ccw(c6818.51,8270.51) 6818.51,8285 ccw(c6818.51,8299.49) v3@6828.76,8289.24 ; v3@6833,8279 cw(c6833,8264.51) 6843.24,8274.76 cw(c6853.49,8285) v3@6839,8285 ; v3@6838.62,8279.38 cw(c6813.09,8253.86) U19.8@6849.19,8253.86 ; v1(6889.47,6409.47) C82.2@6943,6458 ; 6919.61,6436.8 ccw(c6896.44,6462.36) C82.2@6930.9,6460.67 ; 6921.15,6438.19 cw(c6942.35,6414.8) C82.2@6943.9,6446.33 ; v1(7089,6901) 7108,6920 C84.2@7126.54,6920 ; 7097.52,6909.52 cw(c7119.64,6887.4) C84.2@7124.32,6918.33 ; v2(7610.94,8353.94) 7657,8400 C86.2@7666.54,8400 ; R77.1@7611,8215.54 R77.1@7626.54,8200 ; 7628.29,8371.29 cw(c7664.57,8335.01) C86.2@7664.57,8386.32 ; C86.2@7646.56,8389.56 ccw(c7636.11,8400) C86.2@7650.88,8400 ; C89.2@7880,8346.54 7887.4,8353.94 v2(7949.94,8353.94) ; C89.2@7889.68,8338.83 cw(c7926.16,8302.35) 7926.16,8353.94 ; C89.2@7889.68,8358.18 ccw(c7899.92,8368.43) 7899.92,8353.94 ; C117.2@8340,8533.46 8360.54,8554 ; C117.2@8341.63,8535 cw(c8366.37,8528.39) 8366.37,8554 ; C117.2@8342.89,8548.81 ccw(c8346.95,8567.58) 8360.53,8554 ; C117.2@8353.22,8531.9 cw(c8382,8524.21) v3(8382,8554) 8360.54,8554 ; C117.2@8353.67,8536.14 cw(c8377.19,8537.34) 8360.53,8554 ; v3@8377.76,8549.76 ccw(c8367.51,8539.51) 8367.51,8554 ccw(c8367.51,8568.49) v3@8377.76,8558.24
  BottomLayer w16: v2(8946,7800) 8990.88,7844.88 C146.1@9020,7844.88 ; 8960.55,7814.55 cw(c9015.68,7759.43) C146.1@9016.03,7837.39 ; v3(9039.63,6873.37) 9064.06,6873.37 C147.1@9100,6837.43 ; 9062.1,6875.34 cw(c9034.67,6847.91) C147.1@9072.9,6841.39 ; 9062.67,6874.76 ccw(c9096.06,6908.15) C147.1@9096.06,6860.93
  BottomLayer w20: C55.1@5537.43,9580 5544.43,9587 v3(5602,9587) ; C55.1@5552.63,9568.74 cw(c5596.72,9524.65) v3@5596.72,9587 ; C55.1@5552.63,9599.14 ccw(c5581.93,9628.44) 5581.93,9587 ; v3(6087,9206) 6121.03,9171.97 ; v3@6095.13,9197.87 cw(c6028.79,9131.53) C78.1@6122.32,9124.19 ; C78.1@6108.61,9139.27 ccw(c6078.63,9169.25) 6121.03,9169.25 ; C78.1@6121.03,9121.29 6121.03,9171.97 ; 6125.81,9167.19 cw(c6085.69,9127.07) C78.1@6142.26,9122.62 ; C78.1@6136.52,9141.41 cw(c6158.92,9171.97) 6121.03,9171.97 ; FB8.2@7393.02,8277.85 cw(c7370.98,8256.63) 7401.57,8256.05 ; v3(7401,8226) FB8.2@7402,8278.54
  other v2: 4898,6164.54 7900,6858 8631,7012 8316.21,7640.91
  other v3: 7406.54,7855 6888,8073.46 6796,9420 6827,9421 4951,9500
V3.3A: C85.2 C87.2 C88.2 C90.2 FB8.1 U10.25 U10.28 U10.31 U10.36 | length 1233.4
  TopLayer w12: v2(7445.89,8448.43) U10.36@7523.54,8448.43 ; v2(7682.99,8526.54) U10.31@7682.99,8607.87 ; v2(7777.48,8528.05) U10.28@7777.48,8607.87 ; v2(7871.97,8528.97) U10.25@7871.97,8607.87
  BottomLayer w20: FB8.1@7393.15,8362.28 ccw(c7376.62,8378.81) 7400,8378.81 ccw(c7423.38,8378.81) FB8.1@7406.85,8362.28 ; C85.2@7393.15,8437.72 cw(c7376.62,8421.19) 7400,8421.19 cw(c7423.38,8421.19) C85.2@7406.85,8437.72 ; FB8.1@7400,8353.46 C85.2@7400,8446.54 7540,8446.54 C87.2@7620,8526.54 C88.2@7740,8526.54 v2(7871.97,8528.97) ; C85.2@7406.85,8439.69 cw(c7423.38,8423.15) 7423.38,8446.54 cw(c7423.38,8469.92) C85.2@7406.85,8453.38 ; 7600.11,8506.64 cw(c7620,8486.75) C87.2@7620,8514.88 ; C87.2@7604.86,8511.39 ccw(c7591.69,8524.57) C87.2@7610.31,8524.57 ; C87.2@7626.85,8519.69 cw(c7643.38,8503.15) 7643.38,8526.54 cw(c7643.38,8549.92) C87.2@7626.85,8533.38 ; C88.2@7733.15,8519.69 ccw(c7716.62,8503.15) 7716.62,8526.54 ccw(c7716.62,8549.92) C88.2@7733.15,8533.38 ; C88.2@7746.72,8535.48 ccw(c7767.61,8557.15) v2@7768.16,8527.05 ; 7816.32,8527.94 ccw(c7815.88,8551.75) C90.2@7833.03,8535.22 ; 7816.93,8527.95 cw(c7817.35,8505) C90.2@7833.28,8521.53 ; C90.2@7846.72,8535.48 ccw(c7863.24,8552.62) v2@7863.68,8528.82 ; C90.2@7846.97,8521.78 cw(c7863.5,8505.85) v2@7863.08,8528.8
V5: C14.1 C18.2 C30.1 C31.1 C35.1 C36.2 C41.2 C43.1 J3.1 J4.A1 J4.A25 J4.B2 J4.B24 J4.D3 J4.D23 J4.E1 J4.E25 JP13.12 R44.2 R45.1 R46.2 R57.2 U7.2 U9.1 U13.14 U13.15 U13.16 U16.15 U18.1 U20.15 U21.15 | length 3112.3
  TopLayer w8: C36.2@9420,7592.07 cw(c9455.65,7592.07) v2@9433.19,7619.75 ; C36.2@9420,7593.46 C36.2@9420,7615 ; C36.2@9420,7608.86 cw(c9442.03,7608.86) v2@9428.15,7625.96 ; v2@9423.42,7624.04 cw(c9411.69,7623.31) C36.2@9420,7615 ; v2@9429.04,7618.42 ccw(c9428.31,7606.69) C36.2@9420,7615 ; v2(9429.41,7195.59) U16.15@9500,7195.59 ; v2(9429.41,7624.41) C36.2@9420,7615 ; v2@9433.65,7191.35 cw(c9443.9,7181.1) 9443.9,7195.59 cw(c9443.9,7210.08) v2@9433.65,7199.83
  TopLayer w12: R45.1@8153.46,9600 v3(8215,9600) ; R46.2@8153.46,9700 v3(8214,9700) ; R45.1@8165.11,9590.32 cw(c8188.47,9566.96) 8188.47,9600 cw(c8188.47,9633.04) R45.1@8165.11,9609.68 ; R46.2@8165.11,9690.32 cw(c8188.47,9666.96) 8188.47,9700 cw(c8188.47,9733.04) R46.2@8165.11,9709.68 ; v3@8209.76,9695.76 ccw(c8199.51,9685.51) 8199.51,9700 ccw(c8199.51,9714.49) v3@8209.76,9704.24 ; v3@8210.76,9595.76 ccw(c8200.51,9585.51) 8200.51,9600 ccw(c8200.51,9614.49) v3@8210.76,9604.24 ; v3(8214.46,9386.54) R44.2@8260,9386.54 ; v3@8218.71,9382.29 cw(c8228.95,9372.05) 8228.95,9386.54 cw(c8228.95,9401.02) v3@8218.71,9390.78 ; R44.2@8250.32,9376.86 ccw(c8226.96,9353.5) 8226.96,9386.54 ccw(c8226.96,9419.57) R44.2@8250.32,9396.21 ; C31.1@8586,9751 v3(8649,9751) ; C31.1@8587,9675 8645,9675 cw(c8645,9709.3) C31.1@8612.05,9699.76 ; C31.1@8588,9719 v3(8648,9719) ; C31.1@8596.28,9763.37 ccw(c8623.04,9786.13) 8623.04,9751 ; C31.1@8596.59,9706.53 cw(c8622.79,9685.24) 8622.79,9719 ; C31.1@8597.21,9732.67 ccw(c8624.26,9752.59) 8624.26,9719 ; C31.1@8597.2,9736.84 cw(c8625.23,9716.16) 8625.23,9751 ; C31.1@8600.53,9696.42 ccw(c8629.03,9704.67) 8629.03,9675 ; C31.1@8603.6,9666.88 cw(c8623.21,9647.26) 8623.21,9675 ; C31.1@8605.42,9771.15 ccw(c8649,9808.2) v3(8649,9751) ; C31.1@8605.9,9698.96 cw(c8648,9664.77) v3(8648,9719) ; C31.1@8606.85,9729.72 cw(c8649,9698.63) v3(8649,9751) ; C31.1@8606.87,9739.79 ccw(c8648,9770.08) v3(8648,9719) ; C31.1@8610.37,9675 ccw(c8610.37,9723.63) v3@8644.76,9689.24 ; 8639.34,9675 ccw(c8639.34,9694.66) v3@8653.24,9680.76 ; v3@8643.76,9714.76 ccw(c8633.51,9704.51) 8633.51,9719 ccw(c8633.51,9733.49) v3@8643.76,9723.24 ; v3@8644.76,9746.76 ccw(c8634.51,9736.51) 8634.51,9751 ccw(c8634.51,9765.49) v3@8644.76,9755.24 ; R57.2@9113.46,9020 9190,9020 v3(9219,9049) ; R57.2@9125.11,9010.32 cw(c9148.47,8986.96) 9148.47,9020 cw(c9148.47,9053.04) R57.2@9125.11,9029.68 ; v3@9213,9049 cw(c9198.51,9049) 9208.76,9038.76 cw(c9219,9028.51) v3@9219,9043
  TopLayer w40: 7039,9553 v3@7320,9553 ; v3@7060,9048 v3(7062.12,9045.88) C14.1@7159,9045.88 7182.88,9022 U9.1@7429,9022 ; C14.1@7171.07,9054.01 ccw(c7248.35,9131.29) 7248.35,9022 ; 7222.86,9022 ccw(c7222.86,9101.7) C18.2@7279.22,9045.34 ; C18.2@7278.78,9045.34 ccw(c7335.14,9101.7) 7335.14,9022 ; C18.2@7279,9047.54 7304.54,9022
  BottomLayer w8: v2(9429.41,7624.41) U21.15@9500,7624.41 ; v2(9431.59,7124.41) U20.15@9500,7124.41 ; v2@9433.65,7620.17 cw(c9443.9,7609.92) 9443.9,7624.41 cw(c9443.9,7638.9) v2@9433.65,7628.65 ; v2@9435.83,7120.17 cw(c9446.08,7109.92) 9446.08,7124.41 cw(c9446.08,7138.9) v2@9435.83,7128.65
  BottomLayer w20: C43.1@4933.46,9018.35 C43.1@4961,9045.88
  BottomLayer w40: v3(4933.46,8876.54) C41.2@4933.46,8920 4961,8947.54 ; C41.2@4935.46,8919.69 ccw(c4933.05,8947.53) 4961,8947.53 ; C41.2@4935.66,8919.78 ccw(c4874.47,8980.96) 4961,8980.96 ; C43.1@4946.99,9027.93 cw(c4913.16,8994.11) 4961,8994.11 ; C43.1@4946.99,9052.07 ccw(c4913.16,9085.89) 4961,9085.89 ; U18.1@4961,9175 4961,8947.54
  other v3: 7091,9045.88 9261,9049 9262,9083 9221,9084 7052,9553 7309,9553 8649,9685
VCCA_PLL1: C68.2 C72.1 C76.2 FB7.2 U1.27 | length 984.8
  TopLayer w8: v3(6175,8185) U1.27@6274.31,8185.1 ; v3@6180.66,8179.35 cw(c6194.33,8165.71) 6194.31,8185.02 cw(c6194.29,8204.33) v3@6180.65,8190.66
  BottomLayer w8: FB7.2@5820,8173.46 C76.2@6120,8173.46 6131.54,8185 v3(6175,8185) ccw(c6175,8128.17) C76.2@6131.9,8165.21 ; FB7.2@5831.09,8162.37 cw(c5857.87,8135.6) 5857.87,8173.46 cw(c5857.87,8211.33) FB7.2@5831.09,8184.56 ; C68.2@5908.91,8162.37 ccw(c5882.13,8135.6) 5882.13,8173.46 ccw(c5882.13,8211.33) C68.2@5908.91,8184.56 ; C68.2@5931.09,8162.37 cw(c5957.87,8135.6) 5957.87,8173.46 cw(c5957.87,8211.33) C68.2@5931.09,8184.56 ; C72.1@6008.91,8162.37 ccw(c5982.13,8135.6) 5982.13,8173.46 ccw(c5982.13,8211.33) C72.1@6008.91,8184.56 ; C72.1@6031.09,8162.37 cw(c6057.87,8135.6) 6057.87,8173.46 cw(c6057.87,8211.33) C72.1@6031.09,8184.56 ; C76.2@6108.91,8162.37 ccw(c6082.13,8135.6) 6082.13,8173.46 ccw(c6082.13,8211.33) C76.2@6108.91,8184.56 ; C76.2@6119.76,8175.64 cw(c6140.15,8158.12) 6140.15,8185 ; C76.2@6125.83,8170.42 cw(c6157.57,8143.14) 6157.57,8185 ; v3@6169.34,8179.34 ccw(c6155.69,8165.69) 6155.69,8185 ccw(c6155.69,8204.31) v3@6169.34,8190.66
VCCA_PLL2: C42.2 C46.2 C50.1 FB6.2 U1.154 | length 837.7
  TopLayer w12: U1.154@4937.69,8185.1 v3(5008.1,8185.1) ; v3@5003.86,8180.86 ccw(c4993.62,8170.62) 4993.62,8185.1 ccw(c4993.62,8199.59) v3@5003.86,8189.34
  BottomLayer w8: C42.2@5064.64,8185.1 C42.2@5066,8186.46
  BottomLayer w12: v3(5008.1,8185.1) C42.2@5064.64,8185.1 ; v3@5012.34,8180.86 cw(c5022.59,8170.62) 5022.59,8185.1 cw(c5022.59,8199.59) v3@5012.34,8189.34 ; 5031.5,8185.1 cw(c5031.5,8149.99) C42.2@5056.32,8174.82 ; 5034.43,8185.1 ccw(c5034.43,8216.07) C42.2@5056.32,8194.17 ; C42.2@5066,8186.46 FB6.2@5366,8186.46 ; C42.2@5075.68,8176.79 cw(c5099.04,8153.43) 5099.04,8186.46 cw(c5099.04,8219.5) C42.2@5075.68,8196.14 ; C46.2@5156.32,8176.79 ccw(c5132.96,8153.43) 5132.96,8186.46 ccw(c5132.96,8219.5) C46.2@5156.32,8196.14 ; C46.2@5175.68,8176.79 cw(c5199.04,8153.43) 5199.04,8186.46 cw(c5199.04,8219.5) C46.2@5175.68,8196.14 ; C50.1@5256.32,8176.79 ccw(c5232.96,8153.43) 5232.96,8186.46 ccw(c5232.96,8219.5) C50.1@5256.32,8196.14 ; C50.1@5275.68,8176.79 cw(c5299.04,8153.43) 5299.04,8186.46 cw(c5299.04,8219.5) C50.1@5275.68,8196.14 ; FB6.2@5356.32,8176.79 ccw(c5332.96,8153.43) 5332.96,8186.46 ccw(c5332.96,8219.5) FB6.2@5356.32,8196.14
VP0_27MHZ: R49.2 U11.AF14 | length 320.3
  TopLayer w8: R49.2@8448.91,8033.48 cw(c8436.16,8020.73) 8454.19,8020.73 ; U11.AF14@8454.19,7818.25 8454.19,8040.72 R49.2@8460,8046.54 ; 8454.19,7992.67 cw(c8511.9,7992.67) R49.2@8471.09,8033.48 ; 8454.19,8011.98 cw(c8492.58,8011.98) R49.2@8465.43,8039.13
VP0_CLK1: U10.4 U11.AF12 | length 1097.3
  TopLayer w6: U10.4@7711.04,8144.78 ccw(c7702.72,8153.11) 7714.49,8153.11 ccw(c7726.26,8153.11) U10.4@7717.93,8144.78 ; U10.4@7714.49,8100 7714.49,8156 7732.49,8174 7951,8174 8075,8050 v1(8298,8050) ; v1@8294.46,8046.46 ccw(c8285.93,8037.93) 8285.93,8050 ccw(c8285.93,8062.07) v1@8294.46,8053.54 ; U11.AF12@8532.93,7818.25 v1(8532.93,7838.07)
  BottomLayer w6: v1(8298,8050) 8321,8050 v1(8532.93,7838.07) ; v1@8301.54,8046.46 cw(c8310.07,8037.93) 8310.07,8050 cw(c8310.07,8062.07) v1@8301.54,8053.54
VP0_HSYNC: U10.8 U11.AE17 | length 754
  TopLayer w6: U10.8@7837.03,8055.21 cw(c7828.71,8046.89) 7840.47,8046.89 cw(c7852.24,8046.89) U10.8@7843.92,8055.21 ; U10.8@7840.47,8100 7840.47,8030.53 7923,7948 8280,7948 8316,7912 8316,7798.96 U11.AE17@8336.08,7778.88
VP0_VSYNC: U10.7 U11.AC17 | length 879.6
  TopLayer w6: U10.7@7805.53,8055.21 cw(c7797.21,8046.89) 7808.98,8046.89 cw(c7820.74,8046.89) U10.7@7812.42,8055.21 ; U10.7@7808.98,8100 7808.98,8024.02 7915,7918 v1(8265,7918) ; v1@8261.46,7914.46 ccw(c8252.93,7905.93) 8252.93,7918 ccw(c8252.93,7930.07) v1@8261.46,7921.54 ; v1(8315,7721.22) U11.AC17@8336.08,7700.14
  BottomLayer w6: v1@8265,7913 cw(c8265,7900.93) 8273.54,7909.46 cw(c8282.07,7918) v1@8270,7918 ; v1(8265,7918) 8315,7868 v1(8315,7721.22)
VP0D2: U10.16 U11.AF17 | length 774.6
  TopLayer w6: U10.16@8031.42,8322.44 v1(8116.56,8322.44) ; U10.16@8076.2,8318.99 cw(c8084.52,8310.67) 8084.52,8322.44 cw(c8084.52,8334.21) U10.16@8076.2,8325.89 ; v1@8113.02,8318.91 ccw(c8104.49,8310.37) 8104.49,8322.44 ccw(c8104.49,8334.51) v1@8113.02,8325.98 ; v1@8171,8225 cw(c8171,8212.93) 8179.54,8221.46 cw(c8188.07,8230) v1@8176,8230 ; v1(8171,8230) 8336.08,8064.92 U11.AF17@8336.08,7818.25
  BottomLayer w6: v1@8116.56,8317.44 cw(c8116.56,8305.37) 8125.09,8313.91 cw(c8133.63,8322.44) v1@8121.56,8322.44 ; v1(8116.56,8322.44) 8171,8268 v1(8171,8230) ; v1@8167.46,8233.54 ccw(c8158.93,8242.07) 8171,8242.07 ccw(c8183.07,8242.07) v1@8174.54,8233.54
VP0D3: U10.15 U11.AF16 | length 719.3
  TopLayer w6: U10.15@8031.42,8290.94 8177.5,8290.94 8375.45,8093 U11.AF16@8375.45,7818.25 ; U10.15@8076.2,8287.5 cw(c8084.52,8279.18) 8084.52,8290.94 cw(c8084.52,8302.71) U10.15@8076.2,8294.39
VP0D4: U10.14 U11.AE16 | length 727.2
  TopLayer w6: U10.14@8031.42,8259.45 8031.87,8259 8178,8259 8356,8081 8356,7798.33 U11.AE16@8375.45,7778.88 ; U10.14@8076.2,8256 cw(c8083.44,8248.77) 8083.44,8259 ; U10.14@8076.2,8262.9 ccw(c8085.61,8272.3) 8085.61,8259
VP0D5: U10.13 U11.AD16 | length 749.8
  TopLayer w6: U10.13@8031.42,8227.95 8138.05,8227.95 v1(8262,8104) ; U10.13@8076.2,8224.51 cw(c8084.52,8216.19) 8084.52,8227.95 cw(c8084.52,8239.72) U10.13@8076.2,8231.4 ; v1@8257,8104 ccw(c8244.93,8104) 8253.46,8112.54 ccw(c8262,8121.07) v1@8262,8109 ; v1(8356,7758.96) U11.AD16@8375.45,7739.51
  BottomLayer w6: v1@8258.46,8100.46 cw(c8249.93,8091.93) 8262,8091.93 cw(c8274.07,8091.93) v1@8265.54,8100.46 ; v1(8262,8104) 8262,7976 8356,7882 v1(8356,7758.96)
VP0D6: U10.12 U11.AC16 | length 751.5
  TopLayer w6: U10.12@8031.42,8196.46 8127.54,8196.46 v1(8234.79,8089.21) ; U10.12@8076.2,8193.01 cw(c8084.52,8184.69) 8084.52,8196.46 cw(c8084.52,8208.22) U10.12@8076.2,8199.9 ; v1@8229.79,8089.21 ccw(c8217.72,8089.21) 8226.26,8097.74 ccw(c8234.79,8106.28) v1@8234.79,8094.21 ; v1(8356,7719.59) U11.AC16@8375.45,7700.14
  BottomLayer w6: v1@8231.26,8085.67 cw(c8222.72,8077.14) 8234.79,8077.14 cw(c8246.86,8077.14) v1@8238.33,8085.67 ; v1(8234.79,8089.21) 8234.79,7978.21 8335,7878 8335,7740.59 v1(8356,7719.59)
VP0D7: U10.11 U11.AB16 | length 810.6
  TopLayer w6: U10.11@7931.51,8055.21 cw(c7923.19,8046.89) 7934.96,8046.89 cw(c7946.73,8046.89) U10.11@7938.41,8055.21 ; U10.11@7934.96,8100 7934.96,8032.04 7947,8020 v1(8129,8020) ; v1@8125.46,8016.46 ccw(c8116.93,8007.93) 8116.93,8020 ccw(c8116.93,8032.07) v1@8125.46,8023.54 ; v1(8356.22,7680) U11.AB16@8375.45,7660.77
  BottomLayer w6: v1@8129,8015 cw(c8129,8002.93) 8137.54,8011.46 cw(c8146.07,8020) v1@8134,8020 ; v1(8129,8020) 8297,7852 8297,7695 8312,7680 v1(8356.22,7680)
VP0D8: U10.10 U11.AE15 | length 810.2
  TopLayer w6: U10.10@7900.02,8055.21 cw(c7891.7,8046.89) 7903.46,8046.89 cw(c7915.23,8046.89) U10.10@7906.91,8055.21 ; U10.10@7903.47,8100 7903.47,8030.53 7936,7998 v1(8313.08,7998) ; v1@8309.54,7994.46 ccw(c8301.01,7985.93) 8301.01,7998 ccw(c8301.01,8010.07) v1@8309.54,8001.54 ; v1(8394,7799.7) U11.AE15@8414.82,7778.88
  BottomLayer w6: v1@8313.08,7993 cw(c8313.08,7980.93) 8321.61,7989.46 cw(c8330.15,7998) v1@8318.08,7998 ; v1(8313.08,7998) 8394,7917.08 v1(8394,7799.7)
VP0D9: U10.9 U11.AD15 | length 856.1
  TopLayer w6: U10.9@7868.52,8055.21 cw(c7860.2,8046.89) 7871.97,8046.89 cw(c7883.74,8046.89) U10.9@7875.42,8055.21 ; U10.9@7871.97,8100 7871.97,8030.03 7923,7979 v1(8289,7979) ; v1@8285.46,7975.46 ccw(c8276.93,7966.93) 8276.93,7979 ccw(c8276.93,7991.07) v1@8285.46,7982.54 ; v1(8394,7760.33) U11.AD15@8414.82,7739.51
  BottomLayer w6: v1@8289,7974 cw(c8289,7961.93) 8297.54,7970.46 cw(c8306.07,7979) v1@8294,7979 ; v1(8289,7979) 8373,7895 8373,7781.33 v1(8394,7760.33)
XSPCLK: U11.R5 U17.2 | length 814.6
  TopLayer w6: v1(8788,7405.7) U11.R5@8808.52,7385.18 ; v1(9038,7723) 9140,7825 U17.2@9237.64,7825 ; v1@9038,7728 ccw(c9038,7740.07) 9046.54,7731.54 ccw(c9055.07,7723) v1@9043,7723 ; U17.2@9199.91,7818.77 ccw(c9184.87,7803.73) 9184.87,7825 ccw(c9184.87,7846.27) U17.2@9199.91,7831.23
  BottomLayer w6: v1(8788,7405.7) 8788,7447 8815,7474 8815,7588 8858,7631 8946,7631 v1(9038,7723) ; v1@9033,7723 cw(c9020.93,7723) 9029.46,7714.46 cw(c9038,7705.93) v1@9038,7718
XSPCS: U11.T4 U17.1 | length 855.7
  TopLayer w6: v1(8829,7443.44) U11.T4@8847.89,7424.55 ; v1(9088,7860) 9103,7875 U17.1@9237.64,7875 ; v1@9088,7865 ccw(c9088,7877.07) 9096.54,7868.54 ccw(c9105.07,7860) v1@9093,7860 ; U17.1@9199.91,7868.77 ccw(c9184.87,7853.73) 9184.87,7875 ccw(c9184.87,7896.27) U17.1@9199.91,7881.23
  BottomLayer w6: v1(8829,7443.44) 8848,7462.44 8848,7583 8867,7602 8959,7602 9034,7677 9075,7677 9088,7690 v1(9088,7860) ; v1@9084.46,7856.46 cw(c9075.93,7847.93) 9088,7847.93 cw(c9100.07,7847.93) v1@9091.54,7856.46
XSPDI: U11.R4 U17.4 | length 762.2
  TopLayer w6: v1(8829,7404.07) U11.R4@8847.89,7385.18 ; v1(9060,7698) 9087,7725 U17.4@9237.64,7725 ; v1@9060,7703 ccw(c9060,7715.07) 9068.54,7706.54 ccw(c9077.07,7698) v1@9065,7698 ; U17.4@9199.91,7718.77 ccw(c9184.87,7703.73) 9184.87,7725 ccw(c9184.87,7746.27) U17.4@9199.91,7731.23
  BottomLayer w6: v1(8829,7404.07) 8809,7424.07 8809,7451.03 8834.82,7476.85 8834.82,7590.82 8862,7618 8955,7618 9035,7698 v1(9060,7698) ; v1@9056.46,7694.46 ccw(c9047.93,7685.93) 9047.93,7698 ccw(c9047.93,7710.07) v1@9056.46,7701.54
XSPDO: U11.P5 U17.3 | length 2436.5
  TopLayer w6: v1(8789,7326.29) U11.P5@8808.52,7345.81 ; v1(8870,6711) 8889,6730 v1(9238,6730) ; v1@8870,6716 ccw(c8870,6728.07) 8878.54,6719.54 ccw(c8887.07,6711) v1@8875,6711 ; v1@9234.46,6726.46 ccw(c9225.93,6717.93) 9225.93,6730 ccw(c9225.93,6742.07) v1@9234.46,6733.54 ; U17.3@9237.64,7775 v1(9363,7775) ; U17.3@9275.36,7768.77 cw(c9290.41,7753.73) 9290.41,7775 cw(c9290.41,7796.27) U17.3@9275.36,7781.23 ; v1@9359.46,7771.46 ccw(c9350.93,7762.93) 9350.93,7775 ccw(c9350.93,7787.07) v1@9359.46,7778.54
  BottomLayer w6: v1(8789,7326.29) 8826,7289.29 8826,7138 8808,7120 8808,6773 v1(8870,6711) ; v1@8865,6711 ccw(c8852.93,6711) 8861.46,6719.54 ccw(c8870,6728.07) v1@8870,6716 ; v1(9238,6730) 9349,6841 9349,7724 9363,7738 v1(9363,7775) ; v1@9238,6735 ccw(c9238,6747.07) 9246.54,6738.54 ccw(c9255.07,6730) v1@9243,6730 ; v1@9359.46,7771.46 cw(c9350.93,7762.93) 9363,7762.93 cw(c9375.07,7762.93) v1@9366.54,7771.46
pads on no net: J2.6 J4.A15 J4.A17 J4.A19 J4.A21 J4.A23 J4.C8 J4.C10 J4.C16 J4.C18 J4.C20 J4.C22 J4.C24 J4.D25 J5.A1 J5.A2 J5.A3 J5.A4 J5.A5 J5.A6 J5.A7 J5.A8 J5.A9 J5.A10 J5.A11 J5.A12 J5.A13 J5.A14 J5.A15 J5.A19 J5.A20 J5.A21 J5.A22 J5.B2 J5.B4 J5.B5 J5.B6 J5.B8 J5.B10 J5.B12 J5.B14 J5.B19 J5.B20 J5.B21 J5.B22 J5.C1 J5.C2 J5.C3 J5.C4 J5.C5 J5.C6 J5.C7 J5.C8 J5.C9 J5.C10 J5.C11 J5.C12 J5.C13 J5.C14 J5.C15 J5.C16 J5.C17 J5.C19 J5.C20 J5.C21 J5.C22 J5.D1 J5.D2 J5.D3 J5.D5 J5.D7 J5.D9 J5.D11 J5.D13 J5.D15 J5.D19 J5.D21 J5.D22 J5.E1 J5.E2 J5.E3 J5.E4 J5.E5 J5.E6 J5.E7 J5.E8 J5.E9 J5.E10 J5.E11 J5.E12 J5.E13 J5.E14 J5.E15 J5.E19 J5.E20 J5.E21 J5.E22 JP8.6 JP8.7 JP8.8 JP10.3 JP10.5 S2.3 S2.4 U1.18 U1.19 U1.20 U1.21 U1.23 U1.38 U1.123 U1.124 U1.125 U1.126 U1.127 U1.128 U1.131 U1.132 U1.133 U1.134 U1.135 U1.136 U1.137 U1.138 U1.139 U1.140 U1.141 U1.156 U1.158 U1.159 U1.160 U1.161 U1.162 U1.163 U1.166 U1.167 U1.168 U1.169 U2.9 U2.10 U2.13 U2.14 U2.15 U2.30 U2.32 U2.34 U2.36 U2.39 U2.41 U2.43 U3.B8 U3.F9 U3.H10 U3.J9 U4.14 U4.30 U4.57 U4.69 U4.70 U4.73 U5.1 U6.1 U7.5 U10.1 U10.20 U10.22 U10.23 U10.24 U10.26 U10.27 U10.29 U10.34 U10.37 U10.43 U11.A4 U11.A5 U11.A7 U11.A9 U11.A10 U11.A11 U11.A13 U11.A17 U11.AA2 U11.AA3 U11.AA23 U11.AA24 U11.AA25 U11.AA26 U11.AB3 U11.AB11 U11.AB12 U11.AB13 U11.AB14 U11.AB15 U11.AB23 U11.AB24 U11.AB25 U11.AC1 U11.AC4 U11.AC6 U11.AC7 U11.AC8 U11.AC9 U11.AC10 U11.AC11 U11.AC12 U11.AC13 U11.AC14 U11.AC15 U11.AC19 U11.AC20 U11.AC21 U11.AC25 U11.AC26 U11.AD3 U11.AD5 U11.AD6 U11.AD7 U11.AD8 U11.AD9 U11.AD10 U11.AD11 U11.AD12 U11.AD13 U11.AD14 U11.AD17 U11.AD19 U11.AD20 U11.AD21 U11.AD22 U11.AD23 U11.AD25 U11.AD26 U11.AE5 U11.AE6 U11.AE7 U11.AE9 U11.AE11 U11.AE18 U11.AE20 U11.AE21 U11.AE22 U11.AE23 U11.AF3 U11.AF4 U11.AF5 U11.AF6 U11.AF8 U11.AF10 U11.AF18 U11.AF20 U11.AF21 U11.AF23 U11.AF24 U11.B8 U11.B9 U11.B10 U11.B11 U11.B12 U11.B15 U11.B16 U11.B17 U11.C7 U11.C8 U11.C9 U11.C10 U11.C11 U11.C12 U11.C15 U11.C16 U11.C17 U11.D6 U11.D7 U11.D8 U11.D9 U11.D10 U11.D11 U11.D12 U11.D15 U11.D16 U11.D17 U11.E11 U11.E12 U11.E13 U11.E14 U11.L22 U11.M5 U11.M22 U11.N22 U11.P22 U11.R22 U11.R25 U11.R26 U11.T22 U11.T23 U11.W7 U11.W23 U11.W24 U11.Y23 U11.Y24 U11.Y25 U11.Y26 U12.1 U15.1 U16.1 U17.6 U17.7 U20.1 U21.1 U21.36 U21.37 U21.38 U21.39 U21.40 U21.42 U21.43 U21.44 U21.45 U21.46
copper on no net:
  other v4: 4121.02,7758.19 4121.02,8029.84

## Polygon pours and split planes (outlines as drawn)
GND on BottomLayer (hatched 90Degree grid 0 track 20, remove dead copper): 4055,9903 9732,9903 9732,7904 7871,7904 7871,6120 4048,6120
GND on GROUND (split plane): 4026.01,6324.02 4243.02,6324.02 4243.02,6032.02 10266.99,6032.02 10266.99,9906.99 4245.02,9906.99 4245.02,9609.99 4026.01,9609.99 4026.01,8154.02 4564,8154.02 cw(c4564,8139) 4574.63,8149.6 4574.62,8149.62 4676.22,8048.02 5525.78,8048.02 5624.98,8147.22 5624.98,8358 cw(c5640,8358) 5629.4,8368.63 5629.38,8368.62 5945.38,8684.62 5945.37,8684.6 cw(c5956,8674) 5956,8689.01 6110.98,8689.01 6110.98,8782 cw(c6126,8782) 6115.32,8792.56 6204.32,8882.56 cw(c6215,8872) 6214.93,8887.01 6357.86,8888.01 cw(c6358,8873) 6358,8888.01 7905,8888.01 cw(c7905,8873) 7920.02,8873 7920.02,8603 cw(c7905,8603) 7905,8587.99 7587.22,8587.99 7493.62,8494.38 7493.63,8494.4 cw(c7483,8505) 7483,8489.99 7273,8489.99 cw(c7273,8505) 7257.98,8505 7257.98,8559.99 7068.22,8559.99 6985.62,8477.38 6985.63,8477.4 cw(c6975,8488) 6975,8472.99 5963.22,8472.99 5815.02,8324.78 5815.02,8048 cw(c5800,8048) 5810.6,8037.37 5810.62,8037.38 5678.62,7905.38 5678.63,7905.4 cw(c5668,7916) 5668,7900.98 4711.22,7900.98 4513.62,7703.38 4513.63,7703.4 cw(c4503,7714) 4503,7698.98 4026.01,7698.98
AGND on GROUND (split plane): 4026.01,7729.02 4496.78,7729.02 4694.38,7926.62 4694.37,7926.6 cw(c4705,7916) 4705,7931.02 5661.78,7931.02 5784.98,8054.22 5784.98,8331 cw(c5800,8331) 5789.4,8341.63 5789.38,8341.62 5946.38,8498.62 5946.37,8498.6 cw(c5957,8488) 5957,8503.01 6968.78,8503.01 7051.38,8585.62 7051.37,8585.6 cw(c7062,8575) 7062,8590.01 7273,8590.01 cw(c7273,8575) 7288.02,8575 7288.02,8520.01 7476.78,8520.01 7570.38,8613.62 7570.37,8613.6 cw(c7581,8603) 7581,8618.01 7889.98,8618.01 7889.98,8857.99 7446.02,8857.99 7446.02,8697 cw(c7436,8697) 7443.08,8689.92 7417.08,8663.92 cw(c7410,8671) 7410,8660.99 7310,8660.99 cw(c7310,8671) 7299.98,8671 7299.98,8799.99 6229.15,8799.99 6197.02,8767.85 6197.02,8622 cw(c6187,8622) 6187,8611.99 5983.15,8611.99 5703.02,8331.85 5703.02,8108 cw(c5693,8108) 5700.08,8100.92 5572.08,7972.92 cw(c5565,7980) 5565,7969.98 4643.15,7969.98 4477.08,7803.92 cw(c4470,7811) 4470,7800.98 4311,7800.98 cw(c4311,7811) 4302.98,7817.01 4302.98,8123.98 4026.01,8123.98
CVBS on GROUND (split plane): 4323.02,7821.02 4465.85,7821.02 4631.92,7987.08 cw(c4639,7980) 4639,7990.02 5560.85,7990.02 5682.98,8112.15 5682.98,8336 cw(c5693,8336) 5685.92,8343.08 5971.92,8629.08 cw(c5979,8622) 5979,8632.01 6176.98,8632.01 6176.98,8772 cw(c6187,8772) 6179.92,8779.08 6217.92,8817.08 cw(c6225,8810) 6225,8820.01 7310,8820.01 cw(c7310,8810) 7320.02,8810 7320.02,8681.01 7405.85,8681.01 7425.98,8701.15 7425.98,8857.99 6358.05,8857.99 6358.1,8857.99 6358.05,8857.99 6221.31,8857.03 6141.02,8775.83 6141.02,8674 cw(c6126,8674) 6126,8658.99 5962.22,8658.99 5655.02,8351.78 5655.02,8141 cw(c5640,8141) 5650.6,8130.37 5650.62,8130.38 5542.62,8022.38 5542.63,8022.4 cw(c5532,8033) 5532,8017.98 4670,8017.98 cw(c4670,8033) 4659.37,8022.4 4659.38,8022.38 4557.78,8123.98 4323.02,8123.98
V5 on VCC (split plane): 4883.02,8829.01 5005.98,8829.01 5005.98,8869 cw(c5021,8869) 5010.4,8879.63 5010.38,8879.62 5113.38,8982.62 5113.37,8982.6 cw(c5124,8972) 5124,8987.01 9236,8987.01 cw(c9236,8972) 9251.01,8972 9251.01,8126.02 9695,8126.02 cw(c9695,8111) 9710.01,8111 9710.01,7694 cw(c9695,7694) 9695,7678.98 9358.01,7678.98 9358.01,6682.02 9695,6682.02 cw(c9695,6667) 9710.01,6667 9710.01,6085.02 10217.99,6085.02 10217.99,9855.99 6729.02,9855.99 6729.02,9501.89 7328.73,9497.06 cw(c7334,9483) 7349.02,9483 7349.02,9244 cw(c7334,9244) 7334,9228.99 6942.02,9228.99 6942.02,9133 cw(c6927,9133) 6927,9117.99 4883.02,9117.99
V1.4 on VCC (split plane): 8170.02,7030.15 8184.15,7016.02 8190.85,7016.02 8234.92,7060.08 cw(c8242,7053) 8242,7063.02 8668,7063.02 cw(c8668,7053) 8675.08,7060.08 8714.15,7021.02 8777.85,7021.02 8794.99,7038.15 8794.99,7054.85 8727.92,7121.92 cw(c8735,7129) 8724.99,7129 8724.99,7154 cw(c8735,7154) 8727.92,7161.08 8772.99,7206.15 8772.99,7218.85 8750.85,7240.98 8725,7240.98 cw(c8725,7251) 8714.99,7251 8714.99,7356 cw(c8725,7356) 8717.92,7363.08 8761.99,7407.15 8761.99,7467.85 8745.92,7483.92 cw(c8753,7491) 8742.99,7491 8742.99,7563 cw(c8753,7563) 8745.92,7570.08 8778.99,7603.15 8778.99,7630.98 8687.01,7630.98 8687.01,7602 cw(c8677,7602) 8677,7591.98 8526,7591.98 cw(c8526,7602) 8515.99,7602 8515.99,7735.85 8249.92,8001.92 cw(c8257,8009) 8246.99,8009 8246.99,8956.99 7813.02,8956.99 7813.02,8594.01 8002,8594.01 cw(c8002,8584) 8012.02,8584 8012.02,7962.15 8268.15,7706.02 8393,7706.02 cw(c8393,7696) 8400.08,7703.08 8439.08,7664.08 cw(c8432,7657) 8442.01,7657 8442.01,7605 cw(c8432,7605) 8432,7594.98 8255,7594.98 cw(c8255,7605) 8247.92,7597.92 8211.85,7633.98 8164.02,7633.98 8164.02,7540.15 8199.08,7505.08 cw(c8192,7498) 8202.01,7498 8202.01,7476 cw(c8192,7476) 8199.08,7468.92 8174.02,7443.85 8174.02,7413.15 8205.08,7382.08 cw(c8198,7375) 8208.01,7375 8208.01,7327.15 8235.08,7300.08 cw(c8228,7293) 8238.01,7293 8238.01,7277 cw(c8228,7277) 8235.08,7269.92 8170.02,7204.85
V1.5 on VCC (split plane): 5206.02,7706.02 6002.98,7706.02 6002.98,7835 cw(c6018,7835) 6007.4,7845.63 6007.38,7845.62 6524.38,8362.62 6524.37,8362.6 cw(c6535,8352) 6535,8367.01 7388.78,8367.01 7616.38,8594.62 7616.37,8594.6 cw(c7627,8584) 7627,8599.01 7782.98,8599.01 7782.98,8956.99 6807.22,8956.99 6433.62,8583.38 6433.63,8583.4 cw(c6423,8594) 6423,8578.99 6130,8578.99 cw(c6130,8594) 6114.98,8594 6114.98,8798.99 5177.02,8798.99 5177.02,8443.22 5281.62,8338.62 5281.6,8338.63 cw(c5271,8328) 5286.02,8328 5286.02,7971 cw(c5271,7971) 5281.6,7960.37 5281.62,7960.38 5206.02,7884.78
